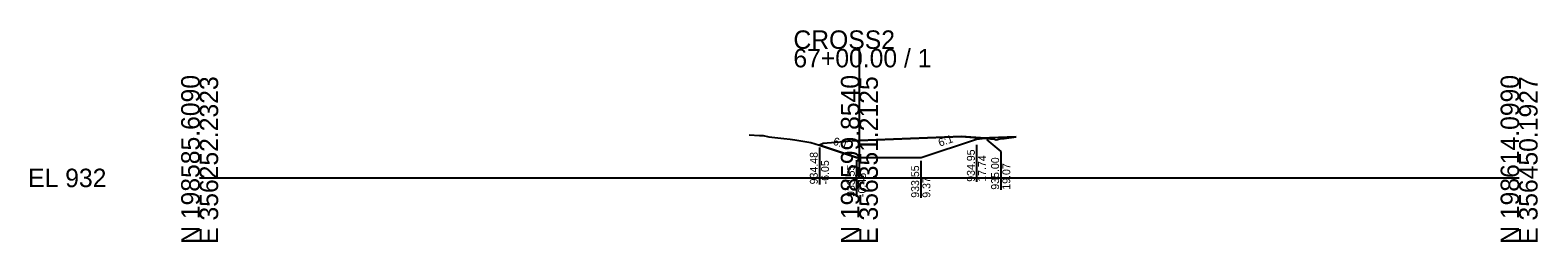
# Model space of a CAD drawing. Extents: x -26 to 203, y -10 to 14021.
# Drawn here: x -25.7 to 202.8, y 7990.3 to 8022.4 of the extents above; entities that cross this region are included whole.
import ezdxf

# ---------------------------------------------------------------- set-up
doc = ezdxf.new("R2010")
doc.units = 0
for name, color, linetype in [('Default', 7, 'Continuous'), ('P_E_XS_Ground', 7, 'Continuous'), ('P_XS', 7, 'Continuous'), ('P_XS_EAR_CommonGrnd', 7, 'Continuous'), ('P_XS_Lane', 7, 'Continuous'), ('P_XS_Rock', 7, 'Continuous')]:
    doc.layers.add(name, color=color, linetype=linetype)

msp = doc.modelspace()

# ---------------------------------------------------------------- linework, layer by layer
at = {"layer": 'Default'}
for p, q in [((100, 8000), (100, 8019.56)), ((0, 8000), (100, 8000)), ((100, 8000), (200, 8000))]:
    msp.add_line(p, q, dxfattribs=at)
at = {"layer": 'P_E_XS_Ground'}
for p, q in [((83.29, 8006.52), (84.86, 8006.43)), ((84.86, 8006.43), (85.44, 8006.41)), ((85.44, 8006.41), (86.29, 8006.24)), ((86.29, 8006.24), (88.57, 8005.98)), ((88.57, 8005.98), (89.52, 8005.86)), ((89.52, 8005.86), (90.2, 8005.76)), ((90.2, 8005.76), (92.65, 8005.38)), ((99.5, 8005.64), (94.5, 8005.24)), ((99.5, 8005.64), (100, 8005.66)), ((100, 8005.66), (115.5, 8006.28)), ((115.5, 8006.28), (120.5, 8005.88)), ((120.5, 8005.88), (120.71, 8005.78)), ((120.71, 8005.78), (120.94, 8005.82)), ((120.94, 8005.82), (121.46, 8005.97)), ((121.46, 8005.97), (121.93, 8005.97)), ((121.93, 8005.97), (123.74, 8006.21)), ((92.65, 8005.38), (93.95, 8004.97)), ((94.5, 8005.24), (93.95, 8004.97))]:
    msp.add_line(p, q, dxfattribs=at)
at = {"layer": 'P_XS'}
for p, q in [((119.74, 8006.05), (119.07, 8006)), ((123.74, 8006.21), (119.74, 8006.05))]:
    msp.add_line(p, q, dxfattribs=at)
at = {"layer": 'P_XS_EAR_CommonGrnd'}
msp.add_lwpolyline([(109.37, 8003.1), (117.74, 8005.89), (119.07, 8006), (115.5, 8006.28), (100, 8005.66), (99.5, 8005.64), (94.5, 8005.24), (93.95, 8004.97), (99.55, 8003.1)], close=True, dxfattribs=at)
at = {"layer": 'P_XS_Lane'}
for p, q in [((109.37, 8003.1), (117.74, 8005.89)), ((119.07, 8006), (117.74, 8005.89)), ((99.55, 8003.1), (93.95, 8004.97)), ((99.55, 8003.1), (109.37, 8003.1))]:
    msp.add_line(p, q, dxfattribs=at)
at = {"layer": 'P_XS_Rock'}
for p, q in [((119.34, 8005.77), (121.42, 8004)), ((93.94, 8004.62), (93.94, 7999.02)), ((117.75, 8005.03), (117.75, 7999.41)), ((121.42, 8004), (121.42, 7998.21)), ((99.55, 8002.71), (99.55, 7997.11)), ((109.3, 8002.58), (109.3, 7996.99))]:
    msp.add_line(p, q, dxfattribs=at)

# ---------------------------------------------------------------- texts
at = {"layer": 'Default'}
for s, p in [('CROSS2', (90, 8019.56)), ('67+00.00 / 1', (90, 8016.76)), ('EL 932', (-26, 7998.6))]:
    msp.add_text(s, height=2.8, dxfattribs=at).set_placement(p)
for s, p in [('N 198585.6090', (0, 7990)), ('E 356252.2323', (2.8, 7990)), ('N 198599.8540', (100, 7990)), ('E 356351.2125', (102.8, 7990)), ('N 198614.0990', (200, 7990)), ('E 356450.1927', (202.8, 7990))]:
    msp.add_text(s, height=2.8, rotation=90, dxfattribs=at).set_placement(p)
at = {"layer": 'P_XS_Rock'}
for s, rotation, p in [('6:1', 341.5651, (95.9, 8005.08)), ('6:1', 18.4349, (112.19, 8004.73)), ('934.48', 90, (93.69, 7999.02)), ('934.95', 90, (117.5, 7999.41)), ('17.74', 90, (119.2, 7999.41)), ('-6.05', 90, (95.39, 7999.02)), ('933.55', 90, (99.3, 7997.11)), ('933.55', 90, (109.05, 7996.99)), ('935.00', 90, (121.17, 7998.21)), ('19.07', 90, (122.87, 7998.21)), ('-0.45', 90, (101, 7997.11)), ('9.37', 90, (110.75, 7996.99))]:
    msp.add_text(s, height=1.2, rotation=rotation, dxfattribs=at).set_placement(p)

doc.saveas('drawing.dxf')
